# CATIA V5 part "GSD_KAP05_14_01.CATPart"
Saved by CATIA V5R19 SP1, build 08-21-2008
Part number: GSD_SPLINE_01
Definition: Beispielmodell Funktion Spline
Description: CATIA V5 Flächenmodellierung  Copyright (c) 2009 Maik Hertha IT Consultants
Bounding box of the stored display mesh (mm): x 14 to 14, y -30 to 50, z -10 to 20
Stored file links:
  C:\Users\Maik\CAD Daten\modelle\gsd_buch_uebung\GSD_KAP05_14_01.CATPart
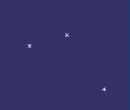
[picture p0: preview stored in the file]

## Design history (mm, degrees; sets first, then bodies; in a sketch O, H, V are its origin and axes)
AxisSystem1: origin (0, 0, 0), X (1, 0, 0), Y (0, 1, 0), Z (0, 0, 1)
Set1
  Plane1: type Offset, Offset 14, RefPlane YZ plane of AxisSystem1
  Point1: type OnPlane, Support Plane1, Direction (0, 1, 0), H -30, V -10
  Point2: type OnPlane, Support Plane1, Direction (0, 1, 0), H -10, V 10
  Point3: type OnPlane, Support Plane1, Direction (0, 1, 0), H 10, V 20
  Point4: type OnPlane, Support Plane1, Direction (0, 1, 0), H 30, V 10
  Point5: type OnPlane, Support Plane1, Direction (0, 1, 0), H 50, V -10
  Line1: type PtDir, Support Plane1, Direction edge [YZ plane of AxisSystem1 | XY plane of AxisSystem1], Start 0, End 35, RefPoint {point type OnPlane, Support Plane1, Direction (0, 1, 0), H 10, V 20}
  Line2: type Angle, Support Plane1, Angle 22, Curve Line1, Start 0, End 36, RefPoint Point3
  Line3: type Angle, Support Plane1, Angle 44, Curve Y axis, Start 0, End 36, RefPoint Point2
Body1 (main body)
